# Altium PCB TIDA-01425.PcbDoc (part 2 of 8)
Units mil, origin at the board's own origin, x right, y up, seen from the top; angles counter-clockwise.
Board outline 7000 x 3600 mil, 6 copper layers (Layer 1 - Top Layer, Layer 2 - GND, Layer 3 - Signal / PWR, Layer 4 - Signal / PWR, Layer 5 - PWR, Layer 6 - Bottom Layer), stack 60.4 mil thick; 495 components, 307 nets, 2058 pads, 1870 vias.
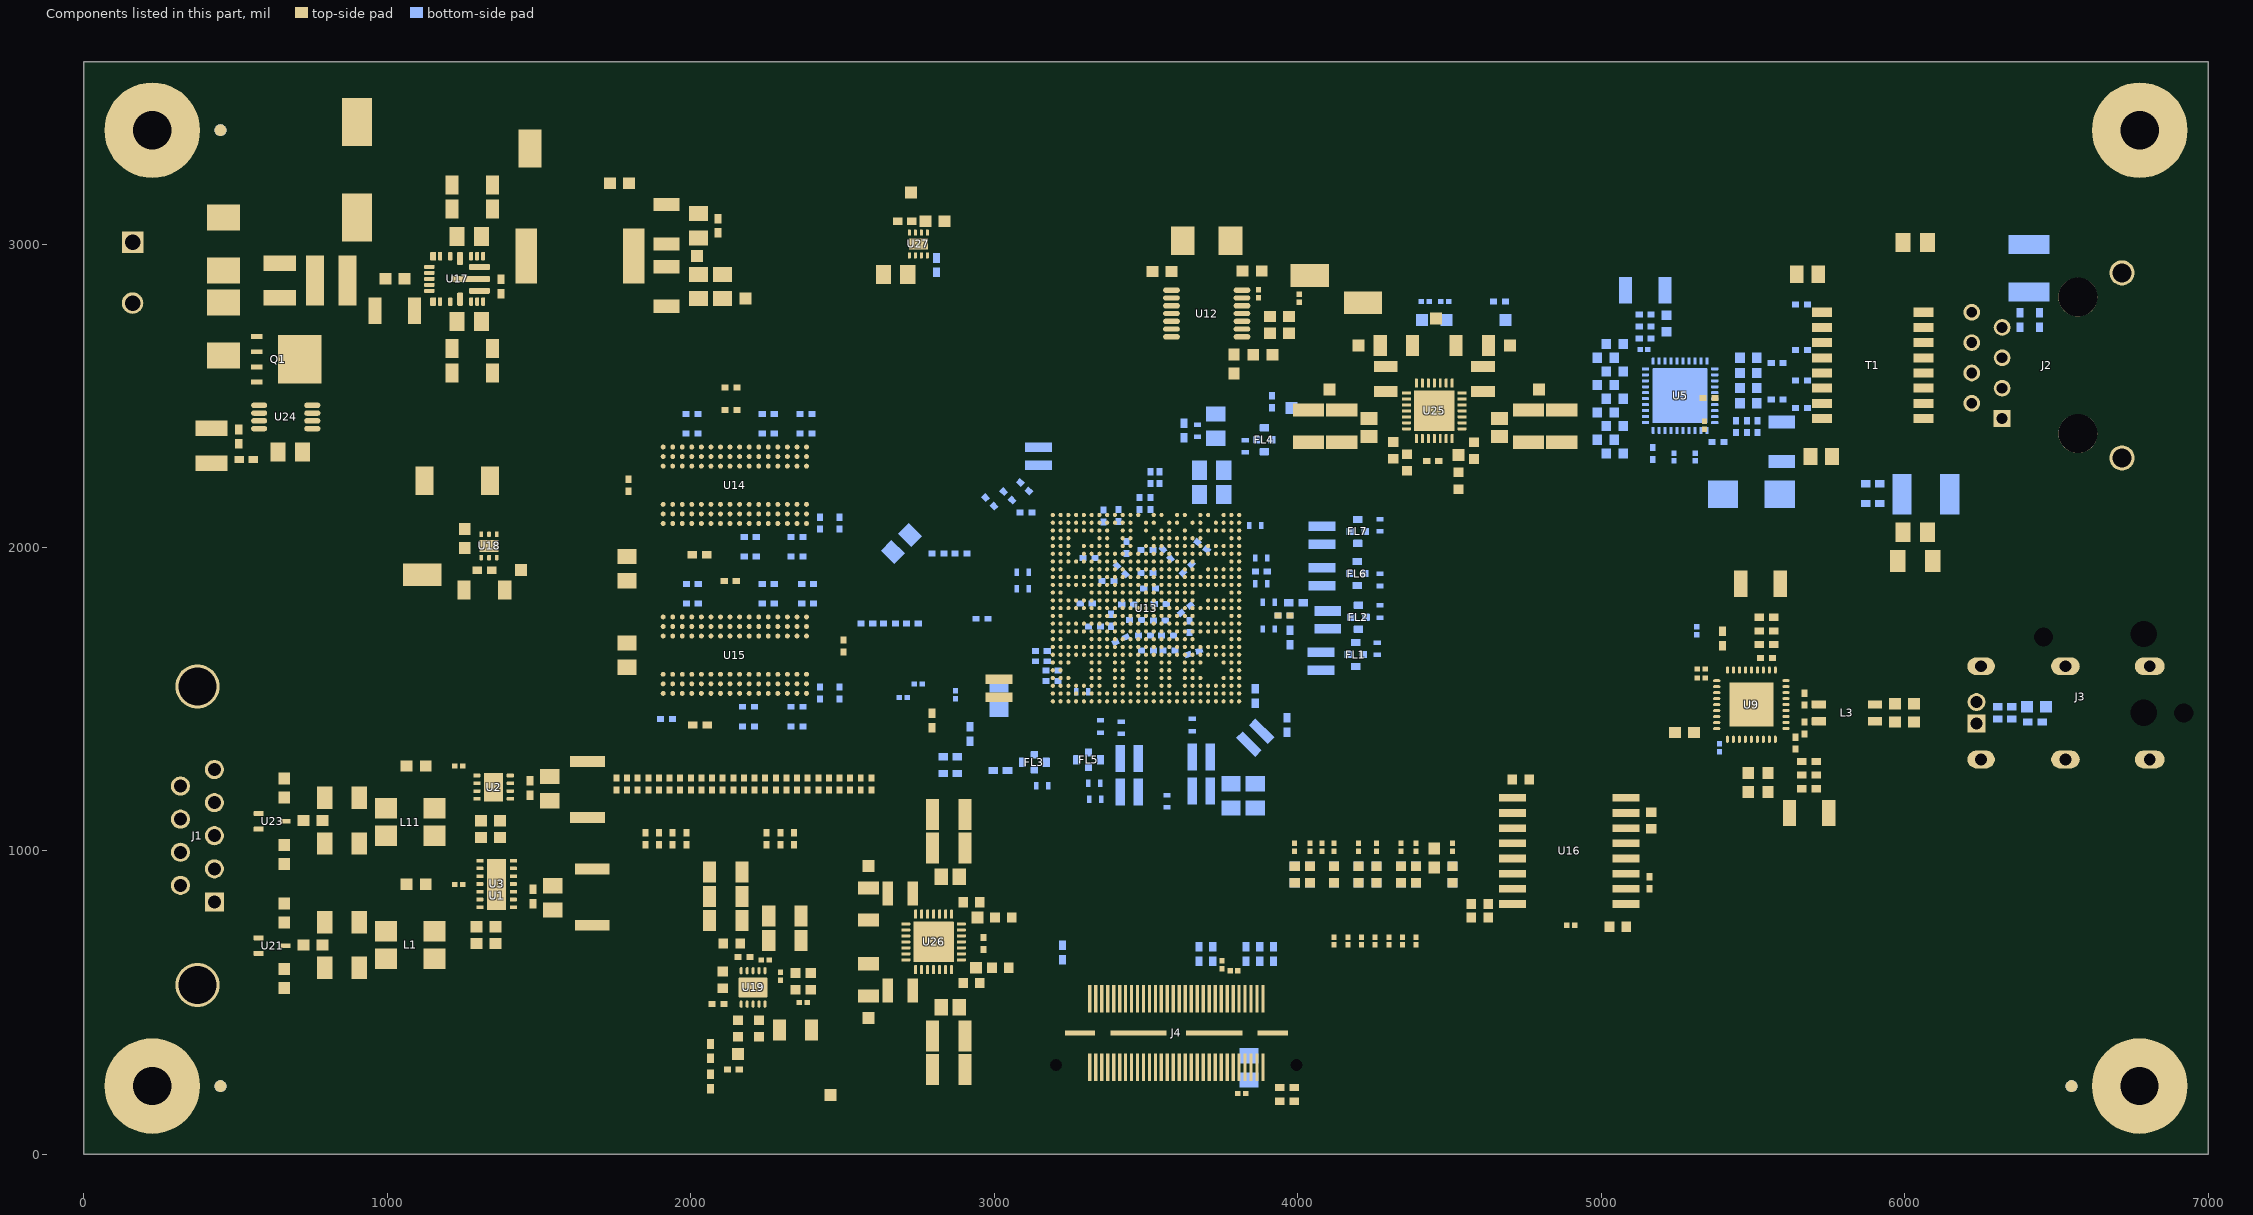
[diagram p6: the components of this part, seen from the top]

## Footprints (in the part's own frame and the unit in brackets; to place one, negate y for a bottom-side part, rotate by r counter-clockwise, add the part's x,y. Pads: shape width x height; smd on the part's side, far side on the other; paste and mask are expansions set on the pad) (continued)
CBD0538A [mm] "BGA, 538-Balls, Body 17x17mm, Pitch 0.65mm"
  round 0.35 smd: A1(-7.8,7.8) A2(-7.15,7.8) A3(-6.5,7.8) A4(-5.85,7.8) A5(-5.2,7.8) A6(-4.55,7.8) A7(-3.9,7.8) A8(-3.25,7.8) A9(-2.6,7.8) A10(-1.95,7.8) A11(-1.3,7.8) A12(-0.65,7.8) A13(0,7.8) A14(0.65,7.8) A15(1.3,7.8) A16(1.95,7.8) A17(2.6,7.8) A18(3.25,7.8) A19(3.9,7.8) A20(4.55,7.8) A21(5.2,7.8) A22(5.85,7.8) A23(6.5,7.8) A24(7.15,7.8) A25(7.8,7.8) AA1(-7.8,-5.2) AA2(-7.15,-5.2) AA3(-6.5,-5.2) AA4(-5.85,-5.2) AA5(-5.2,-5.2) AA6(-4.55,-5.2) AA7(-3.9,-5.2) AA8(-3.25,-5.2) AA9(-2.6,-5.2) AA10(-1.95,-5.2) AA11(-1.3,-5.2) AA12(-0.65,-5.2) AA13(0,-5.2) AA15(1.3,-5.2) AA16(1.95,-5.2) AA18(3.25,-5.2) AA19(3.9,-5.2) AA20(4.55,-5.2) AA21(5.2,-5.2) AA23(6.5,-5.2) AA24(7.15,-5.2) AA25(7.8,-5.2) AB1(-7.8,-5.85) AB2(-7.15,-5.85) AB6(-4.55,-5.85) AB7(-3.9,-5.85) AB8(-3.25,-5.85) AB9(-2.6,-5.85) AB10(-1.95,-5.85) AB11(-1.3,-5.85) AB12(-0.65,-5.85) AB15(1.3,-5.85) AB16(1.95,-5.85) AB18(3.25,-5.85) AB19(3.9,-5.85) AB23(6.5,-5.85) AB24(7.15,-5.85) AB25(7.8,-5.85) AC1(-7.8,-6.5) AC2(-7.15,-6.5) AC3(-6.5,-6.5) AC4(-5.85,-6.5) AC5(-5.2,-6.5) AC6(-4.55,-6.5) AC8(-3.25,-6.5) AC10(-1.95,-6.5) AC11(-1.3,-6.5) AC13(0,-6.5) AC15(1.3,-6.5) AC16(1.95,-6.5) AC18(3.25,-6.5) AC19(3.9,-6.5) AC20(4.55,-6.5) AC21(5.2,-6.5) AC22(5.85,-6.5) AC23(6.5,-6.5) AC24(7.15,-6.5) AC25(7.8,-6.5) AD1(-7.8,-7.15) AD2(-7.15,-7.15) AD3(-6.5,-7.15) AD4(-5.85,-7.15) AD6(-4.55,-7.15) AD7(-3.9,-7.15) AD9(-2.6,-7.15) AD10(-1.95,-7.15) AD12(-0.65,-7.15) AD13(0,-7.15) AD15(1.3,-7.15) AD16(1.95,-7.15) AD17(2.6,-7.15) AD18(3.25,-7.15) AD19(3.9,-7.15) AD20(4.55,-7.15) AD21(5.2,-7.15) AD22(5.85,-7.15) AD23(6.5,-7.15) AD24(7.15,-7.15) AD25(7.8,-7.15) AE1(-7.8,-7.8) AE2(-7.15,-7.8) AE3(-6.5,-7.8) AE5(-5.2,-7.8) AE6(-4.55,-7.8) AE8(-3.25,-7.8) AE9(-2.6,-7.8) AE11(-1.3,-7.8) AE12(-0.65,-7.8) AE14(0.65,-7.8) AE15(1.3,-7.8) AE16(1.95,-7.8) AE17(2.6,-7.8) AE18(3.25,-7.8) AE19(3.9,-7.8) AE20(4.55,-7.8) AE21(5.2,-7.8) AE22(5.85,-7.8) AE23(6.5,-7.8) AE24(7.15,-7.8) AE25(7.8,-7.8) B1(-7.8,7.15) B2(-7.15,7.15) B3(-6.5,7.15) B4(-5.85,7.15) B5(-5.2,7.15) B6(-4.55,7.15) B7(-3.9,7.15) B8(-3.25,7.15) B9(-2.6,7.15) B10(-1.95,7.15) B11(-1.3,7.15) B12(-0.65,7.15) B13(0,7.15) B14(0.65,7.15) B15(1.3,7.15) B16(1.95,7.15) B17(2.6,7.15) B18(3.25,7.15) B19(3.9,7.15) B20(4.55,7.15) B21(5.2,7.15) B22(5.85,7.15) B23(6.5,7.15) B24(7.15,7.15) B25(7.8,7.15) C1(-7.8,6.5) C2(-7.15,6.5) C3(-6.5,6.5) C4(-5.85,6.5) C5(-5.2,6.5) C6(-4.55,6.5) C7(-3.9,6.5) C8(-3.25,6.5) C10(-1.95,6.5) C11(-1.3,6.5) C13(0,6.5) C14(0.65,6.5) C16(1.95,6.5) C17(2.6,6.5) C19(3.9,6.5) C20(4.55,6.5) C21(5.2,6.5) C22(5.85,6.5) C23(6.5,6.5) C24(7.15,6.5) C25(7.8,6.5) D1(-7.8,5.85) D2(-7.15,5.85) D3(-6.5,5.85) D6(-4.55,5.85) D7(-3.9,5.85) D8(-3.25,5.85) D10(-1.95,5.85) D11(-1.3,5.85) D13(0,5.85) D14(0.65,5.85) D16(1.95,5.85) D17(2.6,5.85) D19(3.9,5.85) D20(4.55,5.85) D23(6.5,5.85) D24(7.15,5.85) D25(7.8,5.85) E1(-7.8,5.2) E2(-7.15,5.2) E7(-3.9,5.2) E8(-3.25,5.2) E10(-1.95,5.2) E11(-1.3,5.2) E13(0,5.2) E14(0.65,5.2) E16(1.95,5.2) E17(2.6,5.2) E19(3.9,5.2) E20(4.55,5.2) E24(7.15,5.2) E25(7.8,5.2) F1(-7.8,4.55) F2(-7.15,4.55) F3(-6.5,4.55) F6(-4.55,4.55) F7(-3.9,4.55) F8(-3.25,4.55) F10(-1.95,4.55) F11(-1.3,4.55) F13(0,4.55) F14(0.65,4.55) F16(1.95,4.55) F17(2.6,4.55) F19(3.9,4.55) F20(4.55,4.55) F23(6.5,4.55) F24(7.15,4.55) F25(7.8,4.55) G1(-7.8,3.9) G2(-7.15,3.9) G3(-6.5,3.9) G4(-5.85,3.9) G5(-5.2,3.9) G6(-4.55,3.9) G7(-3.9,3.9) G8(-3.25,3.9) G9(-2.6,3.9) G10(-1.95,3.9) G11(-1.3,3.9) G12(-0.65,3.9) G13(0,3.9) G14(0.65,3.9) G15(1.3,3.9) G16(1.95,3.9) G17(2.6,3.9) G18(3.25,3.9) G19(3.9,3.9) G20(4.55,3.9) G21(5.2,3.9) G22(5.85,3.9) G23(6.5,3.9) G24(7.15,3.9) G25(7.8,3.9) H1(-7.8,3.25) H2(-7.15,3.25) H3(-6.5,3.25) H4(-5.85,3.25) H5(-5.2,3.25) H6(-4.55,3.25) H7(-3.9,3.25) H8(-3.25,3.25) H9(-2.6,3.25) H10(-1.95,3.25) H11(-1.3,3.25) H12(-0.65,3.25) H13(0,3.25) H14(0.65,3.25) H15(1.3,3.25) H16(1.95,3.25) H17(2.6,3.25) H18(3.25,3.25) H19(3.9,3.25) H20(4.55,3.25) H21(5.2,3.25) H22(5.85,3.25) H23(6.5,3.25) H24(7.15,3.25) H25(7.8,3.25) J1(-7.8,2.6) J2(-7.15,2.6) J7(-3.9,2.6) J8(-3.25,2.6) J9(-2.6,2.6) J10(-1.95,2.6) J11(-1.3,2.6) J12(-0.65,2.6) J13(0,2.6) J14(0.65,2.6) J15(1.3,2.6) J16(1.95,2.6) J17(2.6,2.6) J18(3.25,2.6) J19(3.9,2.6) J20(4.55,2.6) J24(7.15,2.6) J25(7.8,2.6) K1(-7.8,1.95) K2(-7.15,1.95) K3(-6.5,1.95) K4(-5.85,1.95) K5(-5.2,1.95) K6(-4.55,1.95) K7(-3.9,1.95) K8(-3.25,1.95) K9(-2.6,1.95) K10(-1.95,1.95) K11(-1.3,1.95) K12(-0.65,1.95) K13(0,1.95) K14(0.65,1.95) K15(1.3,1.95) K16(1.95,1.95) K17(2.6,1.95) K18(3.25,1.95) K19(3.9,1.95) K20(4.55,1.95) K21(5.2,1.95) K22(5.85,1.95) K23(6.5,1.95) K24(7.15,1.95) K25(7.8,1.95) L1(-7.8,1.3) L2(-7.15,1.3) L3(-6.5,1.3) L4(-5.85,1.3) L5(-5.2,1.3) L6(-4.55,1.3) L7(-3.9,1.3) L8(-3.25,1.3) L9(-2.6,1.3) L10(-1.95,1.3) L11(-1.3,1.3) L12(-0.65,1.3) L13(0,1.3) L14(0.65,1.3) L15(1.3,1.3) L16(1.95,1.3) L17(2.6,1.3) L18(3.25,1.3) L19(3.9,1.3) L20(4.55,1.3) L21(5.2,1.3) L22(5.85,1.3) L23(6.5,1.3) L24(7.15,1.3) L25(7.8,1.3) M1(-7.8,0.65) M2(-7.15,0.65) M7(-3.9,0.65) M8(-3.25,0.65) M9(-2.6,0.65) M10(-1.95,0.65) M11(-1.3,0.65) M12(-0.65,0.65) M13(0,0.65) M14(0.65,0.65) M15(1.3,0.65) M16(1.95,0.65) M17(2.6,0.65) M18(3.25,0.65) M19(3.9,0.65) M20(4.55,0.65) M24(7.15,0.65) M25(7.8,0.65) N1(-7.8,0) N2(-7.15,0) N3(-6.5,0) N4(-5.85,0) N5(-5.2,0) N6(-4.55,0) N7(-3.9,0) N8(-3.25,0) N9(-2.6,0) N10(-1.95,0) N11(-1.3,0) N12(-0.65,0) N13(0,0) N14(0.65,0) N15(1.3,0) N16(1.95,0) N17(2.6,0) N18(3.25,0) N19(3.9,0) N20(4.55,0) N21(5.2,0) N22(5.85,0) N23(6.5,0) N24(7.15,0) N25(7.8,0) P1(-7.8,-0.65) P2(-7.15,-0.65) P3(-6.5,-0.65) P4(-5.85,-0.65) P5(-5.2,-0.65) P7(-3.9,-0.65) P8(-3.25,-0.65) P9(-2.6,-0.65) P10(-1.95,-0.65) P11(-1.3,-0.65) P12(-0.65,-0.65) P13(0,-0.65) P14(0.65,-0.65) P15(1.3,-0.65) P16(1.95,-0.65) P17(2.6,-0.65) P18(3.25,-0.65) P19(3.9,-0.65) P20(4.55,-0.65) P21(5.2,-0.65) P22(5.85,-0.65) P23(6.5,-0.65) P24(7.15,-0.65) P25(7.8,-0.65) R1(-7.8,-1.3) R2(-7.15,-1.3) R7(-3.9,-1.3) R8(-3.25,-1.3) R9(-2.6,-1.3) R10(-1.95,-1.3) R11(-1.3,-1.3) R12(-0.65,-1.3) R13(0,-1.3) R14(0.65,-1.3) R15(1.3,-1.3) R16(1.95,-1.3) R17(2.6,-1.3) R18(3.25,-1.3) R19(3.9,-1.3) R20(4.55,-1.3) R24(7.15,-1.3) R25(7.8,-1.3) T1(-7.8,-1.95) T2(-7.15,-1.95) T3(-6.5,-1.95) T4(-5.85,-1.95) T5(-5.2,-1.95) T6(-4.55,-1.95) T7(-3.9,-1.95) T8(-3.25,-1.95) T9(-2.6,-1.95) T10(-1.95,-1.95) T11(-1.3,-1.95) T12(-0.65,-1.95) T13(0,-1.95) T14(0.65,-1.95) T15(1.3,-1.95) T16(1.95,-1.95) T17(2.6,-1.95) T18(3.25,-1.95) T19(3.9,-1.95) T20(4.55,-1.95) T21(5.2,-1.95) T22(5.85,-1.95) T23(6.5,-1.95) T24(7.15,-1.95) T25(7.8,-1.95) U1(-7.8,-2.6) U2(-7.15,-2.6) U3(-6.5,-2.6) U4(-5.85,-2.6) U5(-5.2,-2.6) U6(-4.55,-2.6) U7(-3.9,-2.6) U8(-3.25,-2.6) U9(-2.6,-2.6) U10(-1.95,-2.6) U11(-1.3,-2.6) U12(-0.65,-2.6) U13(0,-2.6) U14(0.65,-2.6) U15(1.3,-2.6) U16(1.95,-2.6) U17(2.6,-2.6) U18(3.25,-2.6) U19(3.9,-2.6) U20(4.55,-2.6) U21(5.2,-2.6) U22(5.85,-2.6) U23(6.5,-2.6) U24(7.15,-2.6) U25(7.8,-2.6) V1(-7.8,-3.25) V2(-7.15,-3.25) V3(-6.5,-3.25) V4(-5.85,-3.25) V5(-5.2,-3.25) V7(-3.9,-3.25) V8(-3.25,-3.25) V9(-2.6,-3.25) V10(-1.95,-3.25) V11(-1.3,-3.25) V12(-0.65,-3.25) V13(0,-3.25) V14(0.65,-3.25) V15(1.3,-3.25) V16(1.95,-3.25) V17(2.6,-3.25) V18(3.25,-3.25) V19(3.9,-3.25) V20(4.55,-3.25) V24(7.15,-3.25) V25(7.8,-3.25) W1(-7.8,-3.9) W2(-7.15,-3.9) W7(-3.9,-3.9) W8(-3.25,-3.9) W9(-2.6,-3.9) W10(-1.95,-3.9) W11(-1.3,-3.9) W12(-0.65,-3.9) W13(0,-3.9) W14(0.65,-3.9) W15(1.3,-3.9) W16(1.95,-3.9) W17(2.6,-3.9) W18(3.25,-3.9) W19(3.9,-3.9) W20(4.55,-3.9) W21(5.2,-3.9) W22(5.85,-3.9) W23(6.5,-3.9) W24(7.15,-3.9) W25(7.8,-3.9) Y1(-7.8,-4.55) Y2(-7.15,-4.55) Y3(-6.5,-4.55) Y4(-5.85,-4.55) Y5(-5.2,-4.55) Y6(-4.55,-4.55) Y7(-3.9,-4.55) Y8(-3.25,-4.55) Y9(-2.6,-4.55) Y10(-1.95,-4.55) Y11(-1.3,-4.55) Y12(-0.65,-4.55) Y13(0,-4.55) Y14(0.65,-4.55) Y15(1.3,-4.55) Y16(1.95,-4.55) Y17(2.6,-4.55) Y18(3.25,-4.55) Y19(3.9,-4.55) Y20(4.55,-4.55) Y21(5.2,-4.55) Y23(6.5,-4.55) Y24(7.15,-4.55) Y25(7.8,-4.55)
  silkscreen extent -8.7,-8.7 8.7,8.7, body extent -8.55,-8.55 8.55,8.55, height 1.3
DCK0003A_N [mm] "SOT23, 3-Leads, Body 2.0x1.25mm, Pitch 0.65mm, Lead Span 2.1mm, IPC Medium Density"
  rrect25% 0.85x0.4 smd: 1(-1.125,0.65) 2(-1.125,-0.65) 3(1.125,0)
  silkscreen extent -1.48,-1.1 0.7,1.1, body extent -1.06,-1 1.06,1, height 1.1
DFE252012P [mm] "TOKO, Pad sizes increased as per request"
  rect 0.9x2 smd: 1(-1.05,0) 2(1.05,0)
  silkscreen extent -0.3,-1.2 0.3,1.2, body extent -1.35,-1.1 1.35,1.1, height 1.2
DGK0008A_N [mm] "TSOP, 8-Leads, Body 3x3mm, Pitch 0.65mm, IPC Medium Density"
  oval 1.35x0.45 smd: 1(-2.225,0.975) 2(-2.225,0.325) 3(-2.225,-0.325) 4(-2.225,-0.975) 5(2.225,-0.975) 6(2.225,-0.325) 7(2.225,0.325) 8(2.225,0.975)
  silkscreen extent -2.75,-1.55 0.95,1.55, body extent -2.45,-1.5 2.45,1.5, height 0.96
DMT0014A [mm] "SON, 14-Leads, Body 3x4.5mm, Pitch 0.65mm"
  rrect33% 0.6x0.3 smd: 1(-1.4,1.95) 2(-1.4,1.3) 3(-1.4,0.65) 4(-1.4,0) 5(-1.4,-0.65) 6(-1.4,-1.3) 7(-1.4,-1.95) 8(1.4,-1.95) 9(1.4,-1.3) 10(1.4,-0.65) 11(1.4,0) 12(1.4,0.65) 13(1.4,1.3) 14(1.4,1.95)
  rrect6% 1.6x4.2 smd paste-1.6: 15(0,0)
  rrect8% 1.47x1.18 on Top Paste: ""(0,1.36) ""(0,-0.02) ""(0,-1.4)
  silkscreen extent -2.1,-2.54 2.1,2.5, body extent -1.5,-2.25 1.5,2.25, height 0.91
DPY0002A [mm] "R-PX2SON-N2"
  rect 0.6x0.5 smd: 1(-0.5,0) 2(0.5,0)
  body extent -0.55,-0.35 0.55,0.35, height 0.4
DRB0008F [mm] "SON, 8-Leads, Body 3x3mm, Pitch 0.65mm, Thermal Pad 2.4x1.6mm, TI Recommended"
  rrect33% 0.6x0.3 smd: 1(-1.4,0.975) 2(-1.4,0.325) 3(-1.4,-0.325) 4(-1.4,-0.975) 5(1.4,-0.975) 6(1.4,-0.325) 7(1.4,0.325) 8(1.4,0.975)
  rrect9% 1.47x1.07 on Top Paste: 9(0,0.635) 9(0,-0.635)
  rrect6% 1.6x2.4 smd paste-1.2: 9(0,0)
  body extent -1.5,-1.5 1.5,1.5, height 0.77
DRC0010J [mm] "SON, 10-Leads, Body 3x3mm, Pitch 0.5mm, Thermal Pad 2.4x1.65mm, TI Recommended"
  rrect100% 0.6x0.24 smd: 1(-1.4,1) 2(-1.4,0.5) 3(-1.4,0) 4(-1.4,-0.5) 5(-1.4,-1) 6(1.4,-1) 7(1.4,-0.5) 8(1.4,0) 9(1.4,0.5) 10(1.4,1)
  rrect6% 1.65x2.4 smd paste-0.825: 11(0,0)
  silkscreen extent -1.7,-1.7 1.7,1.7, body extent -1.5,-1.5 1.5,1.5, height 0.77
DRV0006A [mm] "SON, 6-Leads, Body 2x2mm, Pitch 0.65mm, Thermal Pad 1.6x1mm, TI Recommended"
  rrect33% 0.45x0.3 smd: 1(-0.975,0.65) 2(-0.975,0) 3(-0.975,-0.65) 4(0.975,-0.65) 5(0.975,0) 6(0.975,0.65)
  rrect14% 1x0.7 on Top Paste: 7(0,0.45) 7(0,-0.45)
  rrect10% 1x1.6 smd paste-0.5: 7(0,0)
  silkscreen extent -1.05,-1.2 1.05,1.2, body extent -1.05,-1.05 1.05,1.05, height 0.81
DSG0008B [mm] "SON, 8-Leads, Body 2x2mm, Pitch 0.5mm, Thermal Pad 1.6x0.9mm, TI Recommended"
  rrect14% 0.9x0.7 on Top Paste: 0(0,0.45) 0(0,-0.45)
  rrect40% 0.5x0.25 smd: 1(-0.95,0.75) 2(-0.95,0.25) 3(-0.95,-0.25) 4(-0.95,-0.75) 5(0.95,-0.75) 6(0.95,-0.25) 7(0.95,0.25) 8(0.95,0.75)
  rrect11% 0.9x1.6 smd paste-0.45: 9(0,0)
  silkscreen extent -1.07,-1.15 1.07,1.15, body extent -1,-1 1,1, height 0.77
FCC_disclaimer [mil]
Fiducial10-20 [mm]
  round 1 smd mask+0.5: 1(0,0)
Keystone_1902E [mil] "Hex Standoff, 4-40 threaded, nylon"
  round 1 on Mech4: 0(0,0)
  body extent -145,-126 146,126, height 1001
Label_650x200 [mil] "Thermal Transfer Label"
  silkscreen extent -325,-100 325,100, body extent -325,-100 325,100, height 1
MuRata_DLW43MH [mm] "SMD, 4-Leads, Body 4.5x3.2mm"
  rrect14% 0.7x1.2 smd: 1(-0.7,2.35) 2(-0.7,-2.35) 3(0.7,-2.35) 4(0.7,2.35)
  silkscreen extent -2,-2.35 1.7,2.35, body extent -1.7,-2.35 1.7,2.35, height 2.91
Murata_NFM21PC [mm] "SMD, 3-Leads, Body 2x1.25mm"
  rrect17% 0.6x0.8 smd: 1(-1,0) 3(1,0)
  rrect17% 0.6x0.65 smd: 2(0,-0.625) 2(0,0.625)
  silkscreen extent -1.2,-0.77 1.2,0.77, body extent -1.1,-0.67 1.1,0.67, height 0.95
NDK_NX5032GA [mm] "SMD, 2-Leads Body 5x3.2mm"
  rect 2x2.4 smd: 1(-2,0) 2(2,0)
  silkscreen extent -2.6,-1.7 2.6,1.7, body extent -2.6,-1.7 2.6,1.7, height 1.5
"NY PMS 440 0025 PH" [mm] "4-40 nylon screw and mounting hole"
  round 8 hole 3.2: 1(0,0)
  body extent -3.3,-3.3 3.3,3.3, height 2.69
On-Shore_OSTTA024163 [mm] "TERM BLOCK 2x1, 5.08mm, TH"
  rect 1.8x1.8 hole 1.3: 1(-2.04,-0.5)
  round 1.8 hole 1.3 paste+0: 2(3.04,-0.5)
  silkscreen extent -6.68,-3.18 5.63,4.55, body extent -5.68,-4.6 5.68,4.6, height 13
PAD_1MM_SQUARE [mm]
  rect 1x1 smd: 1(0,0)
PAD_2-92x0-9MM_SMD [mm]
  rect 2.92x0.9 smd: 1(0,0)
PAD_3-2x1-9MM_SMD [mm]
  rect 3.2x1.9 smd: 1(0,0)
Pb-Free_Overlay_Small [mil]
  silkscreen extent -46,-46 46,46
PowerPAK_SO-8L [mm] "based on Vishay recommended land pattern Document 63818 Feb 7, 2012"
  rect 1x0.41 smd: 1(-2.805,1.905) 2(-2.805,0.635) 3(-2.805,-0.635) 4(-2.805,-1.905)
  rect 3.63x4.061 smd: 5(0.805,0)
  Layer 1 - Top Layer region: 2.615,-2.5 3.125,-2.5 3.125,2.5 2.615,2.5
  Layer 1 - Top Layer region: -0.298,2.03 0.298,2.03 0.298,2.64 -0.298,2.64
  Layer 1 - Top Layer region: -0.298,-2.64 0.298,-2.64 0.298,-2.03 -0.298,-2.03
  body extent -3.07,-2.57 3.08,2.57, height 1.21
Pulse_HX1188FNLT [mm] "SMD, 16-Leads, Body 12.7x9.09mm, Pitch 1.27mm"
  rect 1.65x0.76 smd: 1(-4.255,4.445) 2(-4.255,3.175) 3(-4.255,1.905) 4(-4.255,0.635) 5(-4.255,-0.635) 6(-4.255,-1.905) 7(-4.255,-3.175) 8(-4.255,-4.445) 9(4.255,-4.445) 10(4.255,-3.175) 11(4.255,-1.905) 12(4.255,-0.635) 13(4.255,0.635) 14(4.255,1.905) 15(4.255,3.175) 16(4.255,4.445)
  silkscreen extent -4.86,-6.42 4.61,6.42, body extent -4.65,-6.42 4.65,6.42, height 6.13
PW0014A_N [mm] "TSOP, 14-Leads, Body 5x4.4mm, Pitch 0.65mm, IPC Medium Density"
  oval 1.4x0.45 smd: 1(-2.95,1.95) 2(-2.95,1.3) 3(-2.95,0.65) 4(-2.95,0) 5(-2.95,-0.65) 6(-2.95,-1.3) 7(-2.95,-1.95) 8(2.95,-1.95) 9(2.95,-1.3) 10(2.95,-0.65) 11(2.95,0) 12(2.95,0.65) 13(2.95,1.3) 14(2.95,1.95)
  silkscreen extent -3.4,-2.55 1.85,2.55, body extent -3.21,-2.5 3.21,2.5, height 1
RHD0028W [mm] "QFN, 28-Leads, Body 5x5mm, Pitch 0.5mm, Thermal Pad 3.4x3.4mm, TI Recommended"
  rrect42% 0.75x0.25 smd: 1(-2.325,1.5) 2(-2.325,1) 3(-2.325,0.5) 4(-2.325,0) 5(-2.325,-0.5) 6(-2.325,-1) 7(-2.325,-1.5) 15(2.325,-1.5) 16(2.325,-1) 17(2.325,-0.5) 18(2.325,0) 19(2.325,0.5) 20(2.325,1) 21(2.325,1.5)
  rrect42% 0.25x0.75 smd: 8(-1.5,-2.325) 9(-1,-2.325) 10(-0.5,-2.325) 11(0,-2.325) 12(0.5,-2.325) 13(1,-2.325) 14(1.5,-2.325) 22(1.5,2.325) 23(1,2.325) 24(0.5,2.325) 25(0,2.325) 26(-0.5,2.325) 27(-1,2.325) 28(-1.5,2.325)
  rrect3% 3.4x3.4 smd paste-1.7: 29(0,0)
  rrect7% 1.47x1.47 on Top Paste: 29A(0.835,0.835) 29B(-0.835,0.835) 29C(-0.835,-0.835) 29D(0.835,-0.835)
  silkscreen extent -2.68,-2.68 2.68,2.68, body extent -2.58,-2.57 2.57,2.58, height 1.01
RND0036A [mm] "TI"
  oval 0.6x0.25 smd: 1(-2.9,2) 2(-2.9,1.5) 3(-2.9,1) 4(-2.9,0.5) 5(-2.9,0) 6(-2.9,-0.5) 7(-2.9,-1) 8(-2.9,-1.5) 9(-2.9,-2) 19(2.9,-2) 20(2.9,-1.5) 21(2.9,-1) 22(2.9,-0.5) 23(2.9,0) 24(2.9,0.5) 25(2.9,1) 26(2.9,1.5) 27(2.9,2)
  oval 0.25x0.6 smd: 10(-2,-2.9) 11(-1.5,-2.9) 12(-1,-2.9) 13(-0.5,-2.9) 14(0,-2.9) 15(0.5,-2.9) 16(1,-2.9) 17(1.5,-2.9) 18(2,-2.9) 28(2,2.9) 29(1.5,2.9) 30(1,2.9) 31(0.5,2.9) 32(0,2.9) 33(-0.5,2.9) 34(-1,2.9) 35(-1.5,2.9) 36(-2,2.9)
  rect 3.7x3.7 smd paste-1.85: 37(0,0)
  silkscreen extent -3.18,-3.18 3.17,3.2, body extent -3,-3 3,3, height 0.81
RNL0022A_NV [mm] "VQFN, 22 pin, 0.5 mm pitch"
  rrect25% 0.7x0.5 smd paste-0.05 mask-0.05: 1(-1.9,2) 17(1.9,2)
  rrect40% 0.7x0.35 smd paste-0.05 mask-0.05: 2(-1.9,1.425) 3(-1.9,0.575) 15(1.9,0.575) 16(1.9,1.425)
  rrect40% 1.1x0.5 smd paste-0.25 mask-0.05: 4(-1.7,-0.25) 14(1.7,-0.25)
  rrect25% 0.4x0.4 on Top Paste: 4A(-2,-0.25) 4B(-1.4,-0.25) 14A(1.4,-0.25) 14B(2,-0.25)
  rrect57% 0.7x0.35 smd paste-0.05 mask-0.05: 5(-1.9,-1.175) 6(-1.9,-1.675) 7(-1.9,-2.175) 11(1.9,-2.175) 12(1.9,-1.675) 13(1.9,-1.175)
  rrect40% 0.5x1.74 smd paste-0.25 mask-0.05: 8(-1,-1.875) 10(1,-1.875)
  rrect25% 0.4x0.66 on Top Paste: 8A(-1,-1.445) 8B(-1,-2.305) 10A(1,-1.445) 10B(1,-2.305)
  rrect40% 0.5x3.25 smd paste-0.25 mask-0.05: 9(0,-1.125)
  rrect25% 0.4x0.63 on Top Paste: 9A(0,0.12) 9B(0,-0.71) 9C(0,-1.54) 9D(0,-2.37)
  rrect40% 0.35x0.85 smd paste-0.05 mask-0.05: 18(1,2.325) 19(0.5,2.325) 20(0,2.325) 21(-0.5,2.325) 22(-1,2.325)
  silkscreen extent -2.15,-2.65 2.15,2.65, body extent -2,-2.5 2,2.5, height 0.9
RTA0040A [mm] "QFN, 40-Leads, Body 6x6mm, Pitch 0.5mm, NSC Recommended"
  rrect40% 0.6x0.25 smd: 1(-2.9,2.25) 2(-2.9,1.75) 3(-2.9,1.25) 4(-2.9,0.75) 5(-2.9,0.25) 6(-2.9,-0.25) 7(-2.9,-0.75) 8(-2.9,-1.25) 9(-2.9,-1.75) 10(-2.9,-2.25) 21(2.9,-2.25) 22(2.9,-1.75) 23(2.9,-1.25) 24(2.9,-0.75) 25(2.9,-0.25) 26(2.9,0.25) 27(2.9,0.75) 28(2.9,1.25) 29(2.9,1.75) 30(2.9,2.25)
  rrect40% 0.25x0.6 smd: 11(-2.25,-2.9) 12(-1.75,-2.9) 13(-1.25,-2.9) 14(-0.75,-2.9) 15(-0.25,-2.9) 16(0.25,-2.9) 17(0.75,-2.9) 18(1.25,-2.9) 19(1.75,-2.9) 20(2.25,-2.9) 31(2.25,2.9) 32(1.75,2.9) 33(1.25,2.9) 34(0.75,2.9) 35(0.25,2.9) 36(-0.25,2.9) 37(-0.75,2.9) 38(-1.25,2.9) 39(-1.75,2.9) 40(-2.25,2.9)
  rrect8% 1.28x1.28 on Bottom Paste: 41(-1.48,-1.48) 41(-1.48,0) 41(-1.48,1.48) 41(0,-1.48) 41(0,0) 41(0,1.48) 41(1.48,-1.48) 41(1.48,0) 41(1.48,1.48)
  rrect2% 4.6x4.6 smd paste-2.3: 41(0,0)
  silkscreen extent -3.2,-3.18 3.18,3.18, body extent -3,-3 3,3, height 0.81
Samtec_QSH-030-01-X-D-A [mm] "Receptacle, 0.5 mm, 30x2, TH"
  rect 2.27x0.279 smd: 1(-2.865,7.25) 2(2.865,7.25) 3(-2.865,6.75) 4(2.865,6.75) 5(-2.865,6.25) 6(2.865,6.25) 7(-2.865,5.75) 8(2.865,5.75) 9(-2.865,5.25) 10(2.865,5.25) 11(-2.865,4.75) 12(2.865,4.75) 13(-2.865,4.25) 14(2.865,4.25) 15(-2.865,3.75) 16(2.865,3.75) 17(-2.865,3.25) 18(2.865,3.25) 19(-2.865,2.75) 20(2.865,2.75) 21(-2.865,2.25) 22(2.865,2.25) 23(-2.865,1.75) 24(2.865,1.75) 25(-2.865,1.25) 26(2.865,1.25) 27(-2.865,0.75) 28(2.865,0.75) 29(-2.865,0.25) 30(2.865,0.25) 31(-2.865,-0.25) 32(2.865,-0.25) 33(-2.865,-0.75) 34(2.865,-0.75) 35(-2.865,-1.25) 36(2.865,-1.25) 37(-2.865,-1.75) 38(2.865,-1.75) 39(-2.865,-2.25) 40(2.865,-2.25) 41(-2.865,-2.75) 42(2.865,-2.75) 43(-2.865,-3.25) 44(2.865,-3.25) 45(-2.865,-3.75) 46(2.865,-3.75) 47(-2.865,-4.25) 48(2.865,-4.25) 49(-2.865,-4.75) 50(2.865,-4.75) 51(-2.865,-5.25) 52(2.865,-5.25) 53(-2.865,-5.75) 54(2.865,-5.75) 55(-2.865,-6.25) 56(2.865,-6.25) 57(-2.865,-6.75) 58(2.865,-6.75) 59(-2.865,-7.25) 60(2.865,-7.25)
  round 0 hole 1.02 unplated: MH1(2.67,10.065) MH2(2.67,-10.065)
  rect 0.43x2.54 smd: MP1(0,8.065) MP4(0,-8.065)
  rect 0.43x4.7 smd: MP2(0,3.175) MP3(0,-3.175)
  silkscreen extent -3.62,-10.66 3.62,10.66, body extent -3.75,-10.64 3.75,10.67, height 3.25
SIMDAD_1812 [mm] "EPCOS"
  rect 1.7x1.85 smd: 1(-1.15,2.025) 2(-1.15,-2.025) 3(1.15,-2.025) 4(1.15,2.025)
  silkscreen extent -2,-0.8 1.75,0.9, body extent -1.75,-2.6 1.75,2.6, height 3.01
SM_RADIAL_10BMM [mm] "Nichicon 10x10"
  rect 4x2.5 smd: 1(-4,0) 2(4,0)
  silkscreen extent -5.25,-5.25 5.25,5.25, body extent -5.25,-5.25 5.25,5.25, height 10.5
SMB [mil] "Molded Diode, 2-Leads, Body 5.4x3.6mm, IPC Medium Density, based on OnSemi component dimensions"
  rect 85x107.99 smd: 1(-87.01,0) 2(87.01,0)
  silkscreen extent -155,-82 125,82, body extent -106,-71 106,71, height 91
SOIC-16 [mm] "SOIC, 16-Leads, Body 10.3x7.5mm, Pitch 1.27mm"
  rect 2.25x0.65 smd: 1(-4.75,4.445) 2(-4.75,3.175) 3(-4.75,1.905) 4(-4.75,0.635) 5(-4.75,-0.635) 6(-4.75,-1.905) 7(-4.75,-3.175) 8(-4.75,-4.445) 9(4.75,-4.445) 10(4.75,-3.175) 11(4.75,-1.905) 12(4.75,-0.635) 13(4.75,0.635) 14(4.75,1.905) 15(4.75,3.175) 16(4.75,4.445)
  silkscreen extent -4.88,-5.25 3.8,5.44, body extent -3.8,-5.25 3.8,5.25, height 2.66
SRN4012TA [mm] "SMD, 2-Leads, Body 4.2x4.2mm"
  rect 1.5x4.2 smd: 1(-1.35,0) 2(1.35,0)
  silkscreen extent -0.33,-2 0.33,2, body extent -1.99,-1.99 1.99,1.99, height 1.19
TE_1PORT_B1-B [mm] "Header, 1.8mm, 2x1, TH"
  rect 1.5x1.5 hole 1: 1(-0.9,17.35)
  round 1.5 hole 1: 2(0.9,17.35)
  round 0 hole 2.2 unplated: MH1(0,3.35) MH2(6.6,3.35)
  round 0 hole 1.6 unplated: MH3(6.35,11.75) MH4(0,0)
  oval 1.5x2.3 hole 1 slot 1.775 at 90 deg: S1(-3.9,16.963) S4(3.9,16.963)
  oval 1.5x2.4 hole 1 slot 1.89 at 90 deg: S2(-3.9,9.905) S5(3.9,9.905)
  oval 1.5x2.5 hole 1 slot 2 at 90 deg: S3(-3.9,2.85) S6(3.9,2.85)
  silkscreen extent -7.15,-1.8 10,19.3, body extent -7.45,-1.8 10.3,19.3, height 13.5
TE_1734354-1 [mm] "Receptacle, D-Sub, 9 Position, R/A, TH"
  rect 1.6x1.6 hole 1.09: 1(-10.92,5.54)
  round 1.6 hole 1.09: 2(-10.92,2.77) 3(-10.92,0) 4(-10.92,-2.77) 5(-10.92,-5.54) 6(-8.08,4.155) 7(-8.08,1.385) 8(-8.08,-1.385) 9(-8.08,-4.155)
  round 3.7 hole 3.18: 10(-9.5,12.495) 11(-9.5,-12.495)
  silkscreen extent -12.4,-15.4 -1.4,15.4, body extent -12.4,-15.4 6.02,15.4, height 12.5
WE-TPC-XLH2 [mm] "Wurth Elektronik recommended land pattern, 2008-04-11"
  rect 1.8x4.6 smd: 1(-4.5,0) 2(4.5,0)
  silkscreen extent -5.15,-5.15 5.15,5.15, body extent -5.15,-5.15 5.15,5.15, height 3.1

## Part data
3.3V 5V TP1 TP2 TP19 TP50 TP51 TP52 TP53 TP54 TP55 TP56 TP57 TP58 TP59 TP60 TP61 TP62 TP63: "1.0x1.0mm pad, square, SMD", Manufacturer=Any
C1 C160 C163 C248: "CAP, CERM, 56 pF, 50 V, +/- 5%, C0G/NP0, 0603", Cap_Case=0603, Manufacturer=MuRata, Supplier Part Number 1=490-1421-1-ND, TempCo=C0G/NP0, Tolerance_%=5, Value1=Unknown, Value2=50V, ValueDisplayed=56pF
C2 C161: "CAP, CERM, 4700 pF, 50 V, +/- 10%, X7R, AEC-Q200 Grade 1, 0603", Cap_Case=0603, Manufacturer=MuRata, Supplier Part Number 1=490-4932-1-ND, TempCo=X7R, Tolerance_%=10, Value1=Unknown, Value2=50V, ValueDisplayed=4700pF
C3 C4 C7: "CAP, CERM, 0.01 µF, 10 V, +/- 10%, X7R, 0402", Cap_Case=0402, Manufacturer=AVX, Supplier Part Number 1=478-7890-1-ND, TempCo=X7R, Tolerance_%=10, Value1=Unknown, Value2=10V, ValueDisplayed=0.01µF
C5: "CAP, CERM, 0.1 µF, 16 V, +/- 5%, X7R, 0402", Cap_Case=0402, Manufacturer=MuRata, Supplier Part Number 1=490-6327-1-ND, TempCo=X7R, Tolerance_%=5, Value1=Unknown, Value2=16V, ValueDisplayed=0.1µF
C6 C14: "CAP, CERM, 0.1 µF, 50 V, +/- 10%, X7R, AEC-Q200 Grade 1, 0805", Cap_Case=0805, Manufacturer=TDK, Supplier Part Number 1=445-7856-1-ND, TempCo=X7R, Tolerance_%=10, Value1=Unknown, Value2=50V, ValueDisplayed=0.1µF
C8 C11 C12 C187 C190 C270: "CAP, CERM, 0.1 µF, 16 V, +/- 10%, X7R, AEC-Q200 Grade 1, 0402", Cap_Case=0402, Manufacturer=Kemet, Supplier Part Number 1=399-6828-1-ND, TempCo=X7R, Tolerance_%=10, Value1=Unknown, Value2=16V, ValueDisplayed=0.1µF
C9 C10 C21 C27 C98 C99 C100 C101 C109 C110 C111: "CAP, CERM, 1 µF, 6.3 V, +/- 20%, X7R, 0508", Cap_Case=0508, Manufacturer=MuRata, Supplier Part Number 1=490-4354-1-ND, TempCo=X7R, Tolerance_%=20, Value1=Unknown, Value2=6.3V, ValueDisplayed=1µF
C13: "CAP, TA, 10 µF, 10 V, +/- 10%, 1.8 ohm, SMD", Cap_Case=C, Manufacturer=Vishay-Sprague, Supplier Part Number 1=718-1047-1-ND, Tolerance_%=10, Value1="1.8 ohm", Value2=10V, ValueDisplayed=10µF
C15 C32 C34 C36 C42 C48 C49 C51 C59 C124 C125 C126 C127 C128 C129 C130 C149 C150 C151 C152 C153 C154 C155 C156 C157 C158 C159 C189 C195 C239: "CAP, CERM, 0.1 µF, 16 V, +/- 10%, X7R, 0402", Cap_Case=0402, Manufacturer=MuRata, Supplier Part Number 1=490-3261-1-ND, TempCo=X7R, Tolerance_%=10, Value1=Unknown, Value2=16V, ValueDisplayed=0.1µF
C16 C22 C199 C235: "CAP, CERM, 100 pF, 50 V, +/- 5%, C0G/NP0, AEC-Q200 Grade 1, 0402", Cap_Case=0402, Manufacturer=TDK, Supplier Part Number 1=445-5596-1-ND, TempCo=C0G/NP0, Tolerance_%=5, Value1=Unknown, Value2=50V, ValueDisplayed=100pF
C17 C23 C232 C236: "CAP, CERM, 10 µF, 25 V, +/- 20%, X7R, AEC-Q200 Grade 1, 1210", Cap_Case=1210, Manufacturer=TDK, Supplier Part Number 1=445-5720-1-ND, TempCo=X7R, Tolerance_%=20, Value1=Unknown, Value2=25V, ValueDisplayed=10µF
C18 C24 C233 C237: "CAP, CERM, 0.01 µF, 50 V, +/- 10%, X7R, AEC-Q200 Grade 1, 0402", Cap_Case=0402, Manufacturer=TDK, Supplier Part Number 1=445-6893-1-ND, TempCo=X7R, Tolerance_%=10, Value1=Unknown, Value2=50V, ValueDisplayed=0.01µF
C19 C25 C234 C238: "CAP, CERM, 1000 pF, 50 V, +/- 5%, C0G/NP0, AEC-Q200 Grade 1, 0402", Cap_Case=0402, Manufacturer=TDK, Supplier Part Number 1=445-6885-1-ND, TempCo=C0G/NP0, Tolerance_%=5, Value1=Unknown, Value2=50V, ValueDisplayed=1000pF
C20 C26: "CAP, CERM, 0.1 µF, 50 V, +/- 10%, X7R, 0603", Cap_Case=0603, Manufacturer=AVX, Supplier Part Number 1=478-5052-1-ND, TempCo=X7R, Tolerance_%=10, Value1=Unknown, Value2=50V, ValueDisplayed=0.1µF
C28: "CAP, CERM, 4700 pF, 50 V, +/- 10%, X7R, 0603", Cap_Case=0603, Manufacturer=Kemet, Supplier Part Number 1=399-1087-1-ND, TempCo=X7R, Tolerance_%=10, Value1=Unknown, Value2=50V, ValueDisplayed=4700pF
C29 C30: "CAP, CERM, 4.7 µF, 10 V, +/- 20%, X7R, 0805", Cap_Case=0805, Manufacturer=TDK, Supplier Part Number 1=445-1605-1-ND, TempCo=X7R, Tolerance_%=20, Value1=Unknown, Value2=10V, ValueDisplayed=4.7µF
C31 C33 C35 C37 C38 C39 C40 C41 C43 C44 C45 C46 C50 C52 C53 C54 C55 C56 C57 C58 C64: "CAP, CERM, 1 µF, 10 V, +/- 10%, X7S, AEC-Q200 Grade 1, 0402", Cap_Case=0402, Manufacturer=MuRata, Supplier Part Number 1=81-GCM155C71A105KE8D, TempCo=X7S, Tolerance_%=10, Value1=Unknown, Value2=10V, ValueDisplayed=1µF
C47 C61 C62 C71 C72 C73 C74 C75 C76 C77 C78 C79 C87 C88 C89 C90 C91 C92 C93 C94 C95 C96 C97 C102 C103 C104 C105 C106 C114 C115 C116 C117 C118 C119 C123 C133 C134 C135 C136 C137 C138 C139 C140 C142 C143 C144 C146 C148 C162 C181 C182: "CAP, CERM, 0.47 µF, 10 V, +/- 10%, X7S, 0402", Cap_Case=0402, Manufacturer=MuRata, Supplier Part Number 1=490-14427-1-ND, TempCo=X7S, Tolerance_%=10, Value1=Unknown, Value2=10V, ValueDisplayed=0.47µF
C60 C107 C108 C112 C113 C120 C230 C243 C258 C262: "CAP, CERM, 10 µF, 10 V, +/- 10%, X7R, 0805", Cap_Case=0805, Manufacturer=MuRata, Supplier Part Number 1=490-10674-1-ND, TempCo=X7R, Tolerance_%=10, Value1=Unknown, Value2=10V, ValueDisplayed=10µF
C63 C65 C66 C67 C68 C69 C80 C81 C82 C83 C84 C85 C200: "CAP, CERM, 0.1 µF, 16 V, +/- 10%, X7R, 0402", Cap_Case=0402, Manufacturer=MuRata, Supplier Part Number 1=490-4759-2-ND, TempCo=X7R, Tolerance_%=10, Value1=Unknown, Value2=16V, ValueDisplayed=0.1µF
C70 C86: "CAP, CERM, 10 µF, 10 V, +/- 10%, X5R, 0805", Cap_Case=0805, Manufacturer="Taiyo Yuden", Supplier Part Number 1=587-1300-1-ND, TempCo=X5R, Tolerance_%=10, Value1=Unknown, Value2=10V, ValueDisplayed=10µF
C121: "CAP, CERM, 0.47 µF, 6.3 V, +/- 10%, X7R, 0402", Cap_Case=0402, Manufacturer="Taiyo Yuden", Supplier Part Number 1=587-3765-1-ND, TempCo=X7R, Tolerance_%=10, Value1=Unknown, Value2=6.3V, ValueDisplayed=0.47µF
C122 C147: "CAP, CERM, 1 µF, 10 V, +/- 10%, X7S, 0402", Cap_Case=0402, Manufacturer=TDK, Supplier Part Number 1=445-9116-1-ND, TempCo=X7S, Tolerance_%=10, Value1="0.011416 ohm", Value2=10V, ValueDisplayed=1µF
C131 C132: "CAP, CERM, 4700 pF, 50 V, +/- 5%, X7R, 0805", Cap_Case=0805, Manufacturer=AVX, Supplier Part Number 1=478-3770-1-ND, TempCo=X7R, Tolerance_%=5, Value1="0.119 ohm", Value2=50V, ValueDisplayed=4700pF
C141: "CAP, CERM, 4.7 µF, 16 V, +/- 10%, X7R, 0805", Cap_Case=0805, Manufacturer=MuRata, Supplier Part Number 1=490-4522-1-ND, TempCo=X7R, Tolerance_%=10, Value1="0.006 ohm", Value2=16V, ValueDisplayed=4.7µF
C145 C201: "CAP, CERM, 1000 pF, 2000 V, +/- 10%, X7R, 1812", Cap_Case=1812, Manufacturer=AVX, Supplier Part Number 1=581-1812GC102KA11A, TempCo=X7R, Tolerance_%=10, Value1=Unknown, Value2=2000V, ValueDisplayed=1000pF
C164: "CAP, AL, 150 µF, 50 V, +/- 20%, 0.18 ohm, SMD", Cap_Case=10x10, Manufacturer=Nichicon, Supplier Part Number 1=493-2307-1-ND, Tolerance_%=20, Value1="0.18 ohm", Value2=50V, ValueDisplayed=150µF
C165 C167: "CAP, CERM, 4700 pF, 50 V, +/- 10%, X7R, 0402", Cap_Case=0402, Manufacturer=MuRata, Supplier Part Number 1=490-1308-1-ND, TempCo=X7R, Tolerance_%=10, Value1=Unknown, Value2=50V, ValueDisplayed=4700pF
C166: "CAP, CERM, 10 µF, 50 V, +/- 10%, X7R, 1210", Cap_Case=1210, Manufacturer=MuRata, Supplier Part Number 1=490-6544-1-ND, TempCo=X7R, Tolerance_%=10, Value1=Unknown, Value2=50V, ValueDisplayed=10µF
C168: "CAP, CERM, 0.68 µF, 50 V, +/- 10%, X7R, 1210", Cap_Case=1210, Manufacturer=MuRata, Supplier Part Number 1=490-1860-1-ND, TempCo=X7R, Tolerance_%=10, Value1=Unknown, Value2=50V, ValueDisplayed=0.68µF
C169 C171: "CAP, CERM, 10 µF, 50 V, +/- 10%, X7R, 1206", Cap_Case=1206, Manufacturer=Samsung, Supplier Part Number 1=1276-6767-1-ND, TempCo=X7R, Tolerance_%=10, Value1=Unknown, Value2=50V, ValueDisplayed=10µF
C170 C175: "CAP, CERM, 4.7 µF, 50 V, +/- 10%, X7R, 1206", Cap_Case=1206_180, Manufacturer=TDK, Supplier Part Number 1=445-8032-1-ND, TempCo=X7R, Tolerance_%=10, Value1="0.003158 ohm", Value2=50V, ValueDisplayed=4.7µF
C172 C176: "CAP, CERM, 0.047 µF, 50 V, +/- 10%, X7R, 0805", Cap_Case=0805, Manufacturer=MuRata, Supplier Part Number 1=490-1661-1-ND, TempCo=X7R, Tolerance_%=10, Value1=Unknown, Value2=50V, ValueDisplayed=0.047µF
C173 C174: "CAP, CERM, 22 µF, 16 V, +/- 10%, X7R, 1210", Cap_Case=1210_280, Manufacturer=TDK, Supplier Part Number 1=445-3945-1-ND, TempCo=X7R, Tolerance_%=10, Value1="0.002582 ohm", Value2=16V, ValueDisplayed=22µF
C177: "CAP, CERM, 0.01 µF, 16 V, +/- 10%, X7R, 0402", Cap_Case=0402, Manufacturer="AT Ceramics", Supplier Part Number 1=1284-1540-1-ND, TempCo=X7R, Tolerance_%=10, Value1=Unknown, Value2=16V, ValueDisplayed=0.01µF
C178: "CAP, CERM, 0.1 µF, 25 V, +/- 10%, X7R, 0603", Cap_Case=0603, Manufacturer=TDK, Supplier Part Number 1=445-1316-1-ND, TempCo=X7R, Tolerance_%=10, Value1=Unknown, Value2=25V, ValueDisplayed=0.1µF
C179: "CAP, CERM, 2.2 µF, 16 V, +/- 20%, X7S, AEC-Q200 Grade 1, 0603", Cap_Case=0603, Manufacturer=TDK, Supplier Part Number 1=445-16105-1-ND, TempCo=X7S, Tolerance_%=20, Value1=Unknown, Value2=16V, ValueDisplayed=2.2µF
C180: "CAP, CERM, 4.7 µF, 16 V, +/- 10%, X7R, AEC-Q200 Grade 1, 1206", Cap_Case=1206, Manufacturer=MuRata, Supplier Part Number 1=490-6065-1-ND, TempCo=X7R, Tolerance_%=10, Value1=Unknown, Value2=16V, ValueDisplayed=4.7µF
C183: "CAP, CERM, 4.7 µF, 10 V, +/- 10%, X7R, 1210", Cap_Case=1210, Manufacturer=AVX, Supplier Part Number 1=1210ZC475KAT2A-ND, TempCo=X7R, Tolerance_%=10, Value1=Unknown, Value2=10V, ValueDisplayed=4.7µF
C184 C185 C186 C188 C197 C198: "CAP, CERM, 10 µF, 16 V, +/- 10%, X7R, AEC-Q200 Grade 1, 1206_190", Cap_Case=1206, Manufacturer=TDK, Supplier Part Number 1=445-12902-1-ND, TempCo=X7R, Tolerance_%=10, Value1=Unknown, Value2=16V, ValueDisplayed=10µF
C191: "CAP, CERM, 10 pF, 50 V, +/- 5%, C0G/NP0, AEC-Q200 Grade 1, 0603", Cap_Case=0603, Manufacturer=TDK, Supplier Part Number 1=445-5628-1-ND, TempCo=C0G/NP0, Tolerance_%=5, Value1=Unknown, Value2=50V, ValueDisplayed=10pF
C192 C193 C196 C231: "CAP, CERM, 1000 pF, 25 V, +/- 10%, X7R, AEC-Q200 Grade 1, 0201", Cap_Case=0201_033, Manufacturer=TDK, Supplier Part Number 1=445-12085-1-ND, TempCo=X7R, Tolerance_%=10, Value1="2.5722 ohm", Value2=25V, ValueDisplayed=1000pF
C194 C222: "CAP, CERM, 13 pF, 50 V, +/- 5%, C0G/NP0, 0603", Cap_Case=0603, Manufacturer=MuRata, Supplier Part Number 1=490-1406-1-ND, TempCo=C0G/NP0, Tolerance_%=5, Value1=Unknown, Value2=50V, ValueDisplayed=13pF
C224: "CAP, CERM, 2.2 µF, 16 V, +/- 10%, X7R, 0805", Cap_Case=0805, Manufacturer=MuRata, Supplier Part Number 1=490-3906-1-ND, TempCo=X7R, Tolerance_%=10, Value1="0.004 ohm", Value2=16V, ValueDisplayed=2.2µF
C228 C229 C241 C242 C251 C257 C260 C261: "CAP, CERM, 22 µF, 16 V, +/- 10%, X7R, 1210", Cap_Case=1210, Manufacturer=MuRata, Supplier Part Number 1=490-4524-1-ND, TempCo=X7R, Tolerance_%=10, Value1="0.003 ohm", Value2=16V, ValueDisplayed=22µF
C240 C244 C259 C263: "CAP, CERM, 22 µF, 10 V, +/- 10%, X7R, AEC-Q200 Grade 1, 1206", Cap_Case=1206, Manufacturer=MuRata, TempCo=X7R, Tolerance_%=10, Value1=Unknown, Value2=10V, ValueDisplayed=22µF
C245 C246 C264 C265: "CAP, CERM, 2.2 µF, 10 V, +/- 10%, X7R, 0603", Cap_Case=0603, Manufacturer=MuRata, Supplier Part Number 1=490-4520-1-ND, TempCo=X7R, Tolerance_%=10, Value1="0.009 ohm", Value2=10V, ValueDisplayed=2.2µF
C247 C266: "CAP, CERM, 0.1 µF, 25 V, +/- 20%, X7R, 0402", Cap_Case=0402, Manufacturer=TDK, Supplier Part Number 1=445-7349-1-ND, TempCo=X7R, Tolerance_%=20, Value1=Unknown, Value2=25V, ValueDisplayed=0.1µF
C249 C250 C267 C268: "CAP, CERM, 1 µF, 16 V, +/- 10%, X7R, AEC-Q200 Grade 1, 0603", Cap_Case=0603, Manufacturer=MuRata, Supplier Part Number 1=490-5241-6-ND, TempCo=X7R, Tolerance_%=10, Value1=Unknown, Value2=16V, ValueDisplayed=1µF
C252 C253: "CAP, CERM, 0.1 µF, 25 V, +/- 5%, X7R, 0603", Cap_Case=0603, Manufacturer=AVX, Supplier Part Number 1=478-3713-1-ND, TempCo=X7R, Tolerance_%=5, Value1="0.05 ohm", Value2=25V, ValueDisplayed=0.1µF
C255 C256: "CAP, CERM, 10 µF, 16 V, +/- 20%, X7R, 0805", Cap_Case=0805, Manufacturer="Taiyo Yuden", Supplier Part Number 1=587-3319-1-ND, TempCo=X7R, Tolerance_%=20, Value1=Unknown, Value2=16V, ValueDisplayed=10µF
C269: "CAP, CERM, 4.7 µF, 16 V, +/- 10%, X7R, AEC-Q200 Grade 1, 0805", Cap_Case=0805, Manufacturer=MuRata, Supplier Part Number 1=490-5332-1-ND, TempCo=X7R, Tolerance_%=10, Value1=Unknown, Value2=16V, ValueDisplayed=4.7µF
C271: "CAP, CERM, 220 pF, 50 V,+/- 1%, C0G/NP0, 0603", Cap_Case=0603, Manufacturer=AVX, Supplier Part Number 1=478-3719-1-ND, TempCo=C0G/NP0, Tolerance_%=1, Value1="0.083 ohm", Value2=50V, ValueDisplayed=220pF
"CAN1 RX" "CAN1 TX" "CAN2 RX" "CAN2 TX": library part PAD_2.92x0.9MM_SMD, "2.92x0.9mm Pad, SMD", Manufacturer=Any
D2: "Diode, TVS, Uni, 26 V, 42.1 Vc, SMB", Manufacturer="Diodes Inc.", Power_W=5, Supplier Part Number 1=SMBJ26A-FDICT-ND, Value1=5W
D3: "Diode, TVS, Uni, 14 V, 23.2 Vc, SMB", Manufacturer="Diodes Inc.", Power_W=5, Supplier Part Number 1=SMBJ14A-FDICT-ND, Value1=5W
FID1 FID2 FID3 FID4 FID5 FID6: "Fiducial mark.  There is nothing to buy or mount.", Manufacturer=N/A
FL1 FL2 FL3 FL4 FL5 FL6 FL7: "Chip EMIFIL Chip 3-Terminal Capacitor for Large Current for General", Manufacturer=MuRata, Supplier Part Number 1=490-2537-1-ND
"GND 3V3Buck" "GND 5V0Boost": "3.2x1.9mm Pad, SMD", Manufacturer=Any
H1 H2 H3 H4: "Machine Screw, Round, #4-40 x 1/4, Nylon, Philips panhead", DigiKeyPartNumber=H542-ND, Manufacturer="B&F Fastener Supply"
H5 H6 H7 H8: "Standoff, Hex, 1\"L #4-40 Nylon", Manufacturer=Keystone, Supplier Part Number 1=36-1902E-ND
J1: "Receptacle, D-Sub, 9 Position, R/A, TH", Color=Black, Manufacturer="TE Connectivity", Supplier Part Number 1=A35107-ND
J2: "Connector, RJ-45, R/A, TH", Current_A=1.5, Manufacturer="Abracon Corporation", Supplier Part Number 1=535-13279-ND, Voltage_V=125
J3: "Header(shrouded), 6 Power, 2 Signal, TH", Manufacturer="TE Connectivity"
J4: "Receptacle, 0.5 mm, 30x2, Gold, TH", Color=Black, Manufacturer=Samtec, Supplier Part Number 1=SAM8180-ND
J5: "Terminal Block, 2x1, 5.08mm, TH", Manufacturer="On-Shore Technology", Supplier Part Number 1=ED2580-ND
L1 L11: "Coupled inductor, 100 µH, 0.15 A, 1.5 ohm, SMD", Manufacturer=TDK, Supplier Part Number 1=871-B82789C0104N002, ValueDisplayed=100µH
L2 L12 L13 L14: "Inductor, Shielded, 470 nH, 4.7 A, 0.021 ohm, SMD", Manufacturer="MuRata Toko", Value1="0.021 ohm", Value2=4.7A, ValueDisplayed=470nH
L3: "Coupled inductor, 200 µH, 4.5 ohm, AEC-Q200 Grade 2, SMD", Manufacturer=MuRata, Supplier Part Number 1=490-14325-1-ND, ValueDisplayed=200µH
L4: "Inductor, Shielded, Ferrite, 1 µH, 2.2 A, 0.0504 ohm, AEC-Q200 Grade 1, SMD", Manufacturer=Bourns, Supplier Part Number 1=SRN4012TA-1R0MCT-ND, Value1="0.0504 ohm", Value2=2.2A, ValueDisplayed=1µH
L5: "Inductor, Shielded Drum Core, Ferrite, 2.2 µH, 5.9 A, 0.0104 ohm, SMD", Manufacturer="Wurth Elektronik", Supplier Part Number 1=732-1055-1-ND, Value1="0.0104 ohm", Value2=5.9A, ValueDisplayed=2.2µH
L6: "Inductor, Shielded Drum Core, Ferrite, 2.2 µH, 2.55 A, 0.025 ohm, AEC-Q200 Grade 0, SMD", Manufacturer=TDK, Supplier Part Number 1=495-1991-1-ND, Value1="0.025 ohm", Value2=2.55A, ValueDisplayed=2.2µH
LBL1: library part THT-14-423-10, "Thermal Transfer Printable Labels, 0.650\" W x 0.200\" H - 10,000 per roll", Alternate Manufacturer=-, Manufacturer=Brady, Supplier Part Number 1=2065596
Logo2: library part Pb-Free
Logo3: library part FCC_disclaimer, "FCC_disclaimer"
Q1: "MOSFET, N-CH, 40 V, 75 A, PowerPAK_SO-8L", Alternate Manufacturer=None, Manufacturer=Vishay-Siliconix, Supplier Part Number 1=SQJ422EP-T1-GE3-ND, Value1="0.0043 ohm", Value2="67 nC"
R1 R19: "RES, 33.0, 1%, 0.1 W, 0603", Manufacturer="Yageo America", Power_W=0.1, Supplier Part Number 1=311-33.0HRCT-ND, TempCo="200 ppm/C", Tolerance_%=1, Value1=1%, Value2=0.1W, Value_Code=33R0, ValueDisplayed=33.0
R2 R9 R18: "RES, 2.49 k, 1%, 0.05 W, 0201", Manufacturer="Yageo America", Power_W=0.05, Supplier Part Number 1=YAG2338CT-ND, TempCo="200 ppm/C", Tolerance_%=1, Value1=1%, Value2=0.05W, Value_Code=2k49, ValueDisplayed=2.49k
R3 R15 R16 R25 R29 R57 R59 R146: "RES, 0, 5%, 0.05 W, 0201", Manufacturer=Vishay-Dale, Power_W=0.05, Supplier Part Number 1=541-0.0AGCT-ND, TempCo=ppm/C, Tolerance_%=5, Value1=5%, Value2=0.05W, Value_Code=0000, ValueDisplayed=0
R4 R8 R40: "RES, 0, 5%, 0.1 W, 0603", Manufacturer=Panasonic, Power_W=0.1, Supplier Part Number 1=P0.0GCT-ND, TempCo="600 ppm/C", Tolerance_%=5, Value1=5%, Value2=0.1W, Value_Code=0000, ValueDisplayed=0
R5 R7 R150 R151: "RES, 60.4, 1%, 0.25 W, 1206", Manufacturer=Vishay-Dale, Power_W=0.25, Supplier Part Number 1=541-60.4FCT-ND, TempCo="100 ppm/C", Tolerance_%=1, Value1=1%, Value2=0.25W, Value_Code=60R4, ValueDisplayed=60.4
R6 R10 R32 R33 R34 R35 R69 R124: "RES, 10.0 k, 1%, 0.1 W, 0603", Manufacturer="Vishay Draloric", Power_W=0.1, Supplier Part Number 1=541-1784-1-ND, TempCo="100 ppm/C", Tolerance_%=1, Value1=1%, Value2=0.1W, Value_Code=10k0, ValueDisplayed=10.0k
R11 R12 R13 R14 R17 R20 R136 R137 R138 R139 R140 R141 R142 R143: "RES, 49.9, 1%, 0.1 W, 0603", Manufacturer=Vishay-Dale, Power_W=0.1, Supplier Part Number 1=541-49.9HCT-ND, TempCo="100 ppm/C", Tolerance_%=1, Value1=1%, Value2=0.1W, Value_Code=49R9, ValueDisplayed=49.9
R21: "RES, 4.87 k, 1%, 0.05 W, 0201", Manufacturer="Yageo America", Power_W=0.05, Supplier Part Number 1=YAG2711CT-ND, TempCo="200 ppm/C", Tolerance_%=1, Value1=1%, Value2=0.05W, Value_Code=4k87, ValueDisplayed=4.87k
R22 R42 R92 R94: "RES, 75.0, 1%, 0.063 W, 0402", Manufacturer=Vishay-Dale, Power_W=0.063, Supplier Part Number 1=541-75.0LCT-ND, TempCo="100 ppm/C", Tolerance_%=1, Value1=1%, Value2=0.063W, Value_Code=75R0, ValueDisplayed=75.0
R23 R24 R96 R97: "RES, 0, 5%, 0.063 W, 0402", Manufacturer=Vishay-Dale, Power_W=0.063, Supplier Part Number 1=541-0.0JCT-ND, TempCo="200 ppm/C", Tolerance_%=5, Value1=5%, Value2=0.063W, Value_Code=0000, ValueDisplayed=0
R26 R27: "RES, 2.00 k, 1%, 0.1 W, AEC-Q200 Grade 0, 0402", Manufacturer=Panasonic, Power_W=0.1, Supplier Part Number 1=P2.00KLCT-ND, TempCo="100 ppm/C", Tolerance_%=1, Value1=1%, Value2=0.1W, Value_Code=2k00, ValueDisplayed=2.00k
R28: "RES, 100 k, 1%, 0.063 W, 0402", Manufacturer=Vishay-Dale, Power_W=0.063, Supplier Part Number 1=541-100KLCT-ND, TempCo="100 ppm/C", Tolerance_%=1, Value1=1%, Value2=0.063W, Value_Code=100k
R30: "RES, 68.0, 1%, 0.1 W, 0603", Manufacturer="Yageo America", Power_W=0.1, Supplier Part Number 1=311-68.0HRCT-ND, TempCo="200 ppm/C", Tolerance_%=1, Value1=1%, Value2=0.1W, Value_Code=68R0, ValueDisplayed=68.0
R31 R48 R131 R132: "RES, 4.99 k, 1%, 0.05 W, 0201", Manufacturer="Yageo America", Power_W=0.05, Supplier Part Number 1=YAG2712CT-ND, TempCo="200 ppm/C", Tolerance_%=1, Value1=1%, Value2=0.05W, Value_Code=4k99, ValueDisplayed=4.99k
R36 R37: "RES, 240, 1%, 0.1 W, AEC-Q200 Grade 0, 0402", Manufacturer=Panasonic, Power_W=0.1, Supplier Part Number 1=P240LCT-ND, TempCo="100 ppm/C", Tolerance_%=1, Value1=1%, Value2=0.1W, Value_Code=240R, ValueDisplayed=240
R38 R39 R73: "RES, 10.0, 1%, 0.1 W, 0603", Manufacturer=Vishay-Dale, Power_W=0.1, Supplier Part Number 1=541-10.0HCT-ND, TempCo="100 ppm/C", Tolerance_%=1, Value1=1%, Value2=0.1W, Value_Code=10R0, ValueDisplayed=10.0
R41 R91 R93 R145: "RES, 10.0 k, 0.1%, 0.063 W, 0402", Manufacturer=Rohm, Power_W=0.063, Supplier Part Number 1=RHM10.0KCDCT-ND, TempCo="100 ppm/C", Tolerance_%=0.1, Value1=0.1%, Value2=0.063W, Value_Code=10k0, ValueDisplayed=10.0k
R43 R44 R45 R46 R47 R101 R102 R105 R106 R109 R110 R113 R115 R119 R120 R123: "RES, 0, 1%, 0.1 W, AEC-Q200 Grade 0, 0603", Manufacturer="Stackpole Electronics Inc", Power_W=0.1, Supplier Part Number 1=RMCF0603ZT0R00CT-ND, TempCo=ppm/C, Tolerance_%=1, Value1=1%, Value2=0.1W, Value_Code=0
R49: "RES, 100, 1%, 0.063 W, 0402", Manufacturer=Rohm, Power_W=0.063, Supplier Part Number 1=RHM100LCT-ND, TempCo="100 ppm/C", Tolerance_%=1, Value1=1%, Value2=0.063W, Value_Code=100R, ValueDisplayed=100
R50 R51 R52 R53 R54 R55: "RES, 4.70 k, 1%, 0.063 W, 0402", Manufacturer="TE Connectivity", Power_W=0.063, Supplier Part Number 1=A121542CT-ND, TempCo="100 ppm/C", Tolerance_%=1, Value1=1%, Value2=0.063W, Value_Code=4k70, ValueDisplayed=4.70k
R56: "RES, 0, 5%, 0.05 W, 0201", Manufacturer=Vishay-Dale, Power_W=0.05, Supplier Part Number 1=541-0.0AGCT-ND, TempCo=ppm/C, Tolerance_%=5, Value1=5%, Value2=0.05W, Value_Code=0000, ValueDisplayed=DNP
R58: "RES, 4.75 k, 1%, 0.125 W, 0805", Manufacturer=Vishay-Dale, Power_W=0.125, Supplier Part Number 1=541-4.75KCCT-ND, TempCo="100 ppm/C", Tolerance_%=1, Value1=1%, Value2=0.125W, Value_Code=4k75, ValueDisplayed=4.75k
R60: "RES, 100 k, 0.5%, 0.1 W, 0805", Manufacturer="Susumu Co Ltd", Power_W=0.1, Supplier Part Number 1=RR12P100KDCT-ND, TempCo="25 ppm/C", Tolerance_%=0.5, Value1=0.5%, Value2=0.1W, Value_Code=100k
R61: "RES, 3.0, 5%, 0.1 W, 0603", Manufacturer=Vishay-Dale, Power_W=0.1, Supplier Part Number 1=541-3.0GCT-ND, TempCo="200 ppm/C", Tolerance_%=5, Value1=5%, Value2=0.1W, Value_Code=3R00, ValueDisplayed=3.0
R62 R63 R64 R65 R66 R67 R68 R71 R72 R74 R76 R77 R78 R80 R81 R82 R83 R84 R85 R86 R87 R88 R89 R90: "RES, 49.9, 1%, 0.063 W, 0402", Manufacturer=Vishay-Dale, Power_W=0.063, Supplier Part Number 1=541-49.9LCT-ND, TempCo="100 ppm/C", Tolerance_%=1, Value1=1%, Value2=0.063W, Value_Code=49R9, ValueDisplayed=49.9
R70: "RES, 100 k, 1%, 0.1 W, 0603", Manufacturer="Yageo America", Power_W=0.1, Supplier Part Number 1=311-100KHRCT-ND, TempCo="200 ppm/C", Tolerance_%=1, Value1=1%, Value2=0.1W, Value_Code=100k
R75 R79: "RES, 10.0 k, 1%, 0.1 W, 0603", Manufacturer=Vishay-Dale, Power_W=0.1, Supplier Part Number 1=541-10.0KHCT-ND, TempCo="100 ppm/C", Tolerance_%=1, Value1=1%, Value2=0.1W, Value_Code=10k0, ValueDisplayed=10.0k
R95: "RES, 1.00 M, 1%, 0.25 W, 1206", Manufacturer="Yageo America", Power_W=0.25, Supplier Part Number 1=311-1.00MFRCT-ND, TempCo="100 ppm/C", Tolerance_%=1, Value1=1%, Value2=0.25W, Value_Code=1M00, ValueDisplayed=1.00M
R98: "RES, 91, 5%, 0.1 W, 0603", Manufacturer=Vishay-Dale, Power_W=0.1, Supplier Part Number 1=541-91GCT-ND, TempCo="200 ppm/C", Tolerance_%=5, Value1=5%, Value2=0.1W, Value_Code=91R0, ValueDisplayed=91
R99 R100 R103 R104 R107 R108 R111 R112 R116 R117 R118 R121 R122 R125 R126 R128 R129: "RES, 10.0 k, 1%, 0.05 W, 0201", Manufacturer=Vishay-Dale, Power_W=0.05, Supplier Part Number 1=541-10.0KAABCT-ND, TempCo="100 ppm/C", Tolerance_%=1, Value1=1%, Value2=0.05W, Value_Code=10k0, ValueDisplayed=10.0k
R114: "RES, 100, 1%, 0.05 W, 0201", Manufacturer="Yageo America", Power_W=0.05, Supplier Part Number 1=311-100MCT-ND, TempCo="200 ppm/C", Tolerance_%=1, Value1=1%, Value2=0.05W, Value_Code=100R, ValueDisplayed=100
R127: "RES, 2.2 k, 5%, 0.05 W, 0201", Manufacturer="Yageo America", Power_W=0.05, Supplier Part Number 1=311-2.2KNCT-ND, TempCo="200 ppm/C", Tolerance_%=5, Value1=5%, Value2=0.05W, Value_Code=2k20, ValueDisplayed=2.2k
R133 R134 R135: "RES, 22, 5%, 0.063 W, 0402", Manufacturer=Vishay-Dale, Power_W=0.063, Supplier Part Number 1=541-22JCT-ND, TempCo="200 ppm/C", Tolerance_%=5, Value1=5%, Value2=0.063W, Value_Code=22R0, ValueDisplayed=22
R147: "RES, 2.49 k, 1%, 0.063 W, 0402", Manufacturer=Vishay-Dale, Power_W=0.063, Supplier Part Number 1=541-2.49KLCT-ND, TempCo="100 ppm/C", Tolerance_%=1, Value1=1%, Value2=0.063W, Value_Code=2k49, ValueDisplayed=2.49k
R148: "RES, 2.49 k, 1%, 0.1 W, 0603", Manufacturer=Vishay-Dale, Power_W=0.1, Supplier Part Number 1=541-2.49KHCT-ND, TempCo="100 ppm/C", Tolerance_%=1, Value1=1%, Value2=0.1W, Value_Code=2k49, ValueDisplayed=2.49k
SCL_CLK SDA_CLK: library part PAD_3.2x1.9MM_SMD, "3.2x1.9mm Pad, SMD", Manufacturer=Any
T1: "Transformer, 350 uH, SMT", Manufacturer="Pulse Engineering", Supplier Part Number 1=553-2208-1-ND, ValueDisplayed=350µH
TP64: library part PAD_1MM_SQUARE, "1.0x1.0mm pad, square, SMD", Manufacturer=Any
U1 U2: "Automotive Fault Protected CAN Transceiver With Flexible Data-Rate, DRB0008F (VSON-8)", Alternate Manufacturer="Texas Instruments", Alternate PartNumber=TCAN1042VDRBTQ1
U3: "Automotive High Speed Dual CAN Transceiver, DMT0014A (VSON-14)", Alternate Manufacturer="Texas Instruments"
U4 U6 U7 U8 U10 U11: "Automotive 1-Channel ESD in 0402 Package With 12pF Capacitance and 6V Breakdown, DPY0002A (X1SON-2)", Alternate Manufacturer="Texas Instruments"
U5: "PHYTER Extended Temperature Single Port 10/100 Mb/s Ethernet Physical Layer Transceiver, RTA0040A (WQFN-40)", Alternate Manufacturer="Texas Instruments", Alternate PartNumber=DP83848QSQ/NOPB
U9: "DP83TC811,RND0036A", Alternate Manufacturer="Texas Instruments"
U12: "Programmable 1-PLL VCXO Clock Synthesizer with 2.5-V or 3.3-V LVCMOS Outputs, PW0014A (TSSOP-14)", Alternate Manufacturer="Texas Instruments"
U13: "Infotainment Applications Processor, CBD0538A (BGA-538)", Alternate Manufacturer="Texas Instruments"
U14 U15: "SDRAM 1GBIT 933MHZ 96FBGA", Manufacturer="Micron Technology", Supplier Part Number 1="MT41K64M16TW-107 AAT:J-ND"
U16: "256 Mbit (32 Mbyte) 3.0V SPI Flash Memory", Manufacturer="Cypress Semiconductor", Supplier Part Number 1=S25FL256SAGMFB010-ND
U17: "2.5/3.5A, 36 V Synchronous, 2.1MHz, Automotive Step Down DC-DC Converter, RNL0022A (VQFN-HR-22)", Alternate Manufacturer="Texas Instruments", Alternate PartNumber=LM536253QRNLTQ1
U18: "Automotive Catalog 5V, 400mA, 4MHz Step-Up DC/DC Converter, DRV0006A", Alternate Manufacturer="Texas Instruments"
U19: "Single Output Automotive LDO, 3 A, 2.3 to 3.5 V Input, with DDR Termination, 10-pin SON (DRC), -40 to 125 degC, Green (RoHS & no Sb/Br)", Alternate Manufacturer="Texas Instruments", Alternate PartNumber=Equivalent, Power Good=TRUE, Rating=Automotive, Supplier Part Number 1=296-25411-2-ND
U21 U23: "ESD Protection Array for AC Signal Data Interface, 2 Channels, -40 to +85 degC, 3-pin SC70 (DCK), Green (RoHS & no Sb/Br)", Alternate Manufacturer="Texas Instruments", Alternate PartNumber=Equivalent, Breakdown Voltage(Min)(V)=+/-14, IO Capacitance(Typ)(pF)=15, IO Leakage Current(nA)=50, Supplier Part Number 1=296-25281-2-ND
U24: "Zero Iq Reverse Polarity Protection Smart Diode Controller, DGK0008A (VSSOP-8)", Alternate Manufacturer="Texas Instruments"
U25: "Dual High-Current Buck Converters And Dual Linear Regulators, RHD0028W (VQFN-28)", Alternate Manufacturer="Texas Instruments"
U26: library part CMP-0013819-2, "Dual High-Current Buck Converters And Dual Linear Regulators, RHD0028W (VQFN-28)", Alternate Manufacturer="Texas Instruments"
U27: "5.5V, 4A, 16mO Automotive Load Switch With Adjustable Rise Time and Optional Quick Output Discharge, DSG0008B (WSON-8)", Alternate Manufacturer="Texas Instruments"
Y1: "Crystal, 25MHz,  SMD", Frequency=25MHz, Frequency Stability=±30ppm, Manufacturer=NDK, Supplier Part Number 1=644-1274-1-ND
ZZ1: library part AssemblyNoteLabel, Alternate Manufacturer=-
ZZ2 ZZ3 ZZ4: library part AssemblyNote, Alternate Manufacturer=-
